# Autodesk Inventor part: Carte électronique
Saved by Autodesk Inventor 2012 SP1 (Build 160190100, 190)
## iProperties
Created: 2014-12
Part Number: Carte électronique
Material: Default
Document SubType Name: Modeling
Designer: Bruno
Density: 1 g/cm^3
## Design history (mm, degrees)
node "Carte électronique1"
node "Carte électronique"
node "Carte électronique_1"
node "Base1"
node "Base2"
